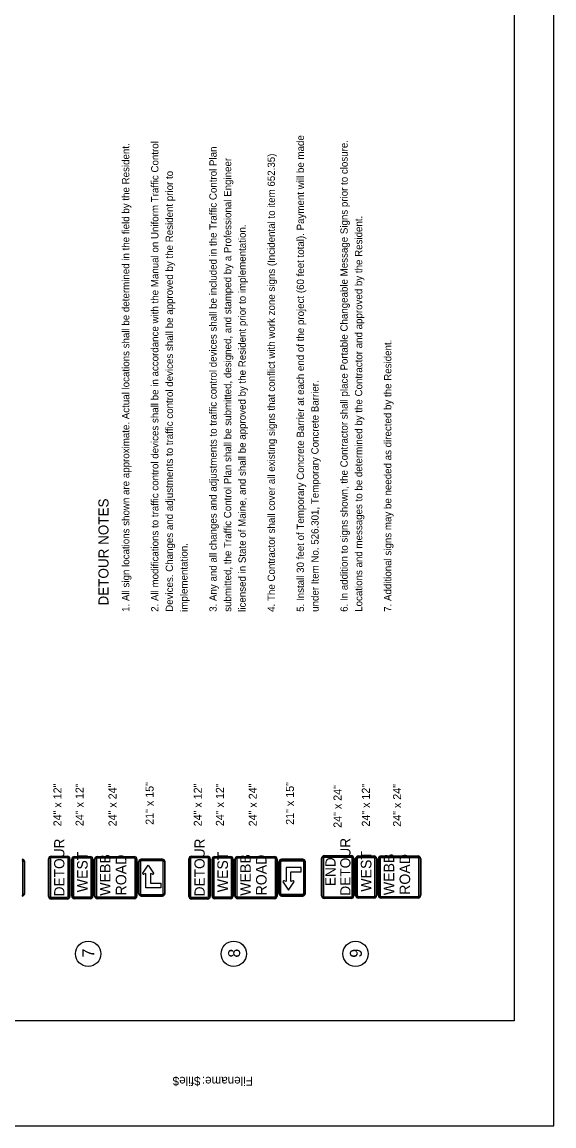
# Model space of a CAD drawing. Extents: x 1149904 to 1171904, y 589308 to 623636.
# Drawn here: x 1163721 to 1171904, y 589308 to 606292 of the extents above; entities that cross this region are included whole.
import ezdxf

# ---------------------------------------------------------------- set-up
doc = ezdxf.new("R2010")
doc.units = 0
for name, color, linetype in [('ANNOTATION', 7, 'Continuous'), ('BORDER', 7, 'Continuous'), ('D_Text_Standard', 7, 'Continuous'), ('Default', 7, 'Continuous'), ('PLOT BOUNDARY', 7, 'Continuous'), ('SIGNS TRAFFIC', 7, 'Continuous')]:
    doc.layers.add(name, color=color, linetype=linetype)

msp = doc.modelspace()

# ---------------------------------------------------------------- linework, layer by layer
at = {"layer": 'BORDER'}
msp.add_lwpolyline([(1150292, 590926), (1150292, 622926), (1171292, 622926), (1171292, 590926)], close=True, dxfattribs=at)
at = {"layer": 'D_Text_Standard'}
for centre in [(1164738, 591956), (1166978, 591956), (1168852, 591955)]:
    msp.add_circle(centre, 195, dxfattribs=at)
at = {"layer": 'PLOT BOUNDARY'}
msp.add_lwpolyline([(1171904, 589308), (1171904, 623308), (1149904, 623308), (1149904, 589308)], close=True, dxfattribs=at)
at = {"layer": 'SIGNS TRAFFIC'}
for p, q in [((1168013, 593215), (1168013, 593286)), ((1165854, 593042), (1165854, 592971))]:
    msp.add_line(p, q, dxfattribs=at)
for points in [[(1164169, 593458), (1164417, 593458)], [(1164169, 593458), (1164417, 593458)], [(1166328, 593458), (1166576, 593458)], [(1166328, 593458), (1166576, 593458)], [(1168371, 593467), (1168784, 593467)], [(1168371, 593467), (1168784, 593467)], [(1168371, 593457), (1168784, 593457)], [(1168893, 593462), (1169136, 593462)], [(1168893, 593462), (1169136, 593462)], [(1169245, 593462), (1169813, 593462)], [(1169245, 593462), (1169813, 593462)], [(1163735, 592885), (1163735, 593372)], [(1163752, 593372), (1163752, 592885)], [(1163762, 592885), (1163762, 593372)], [(1164128, 592840), (1164128, 593417)], [(1164128, 592840), (1164128, 593417)], [(1164139, 592840), (1164139, 593417)], [(1164156, 593417), (1164156, 592840)], [(1164169, 593448), (1164417, 593448)], [(1164417, 593431), (1164169, 593431)], [(1164431, 592840), (1164431, 593417)], [(1164448, 593417), (1164448, 592840)], [(1164458, 593417), (1164458, 592840)], [(1164458, 593417), (1164458, 592840)], [(1164485, 592844), (1164485, 593413)], [(1164485, 592844), (1164485, 593413)], [(1164495, 592844), (1164495, 593413)], [(1164512, 593413), (1164512, 592844)], [(1164526, 593453), (1164770, 593453)], [(1164526, 593453), (1164770, 593453)], [(1164526, 593443), (1164770, 593443)], [(1164770, 593426), (1164526, 593426)], [(1164783, 592844), (1164783, 593413)], [(1164800, 593413), (1164800, 592844)], [(1164810, 593413), (1164810, 592844)], [(1164810, 593413), (1164810, 592844)], [(1164837, 592844), (1164837, 593413)], [(1164837, 592844), (1164837, 593413)], [(1164847, 592844), (1164847, 593413)], [(1164864, 593413), (1164864, 592844)], [(1164878, 593453), (1165447, 593453)], [(1164878, 593453), (1165447, 593453)], [(1164878, 593443), (1165447, 593443)], [(1165447, 593426), (1164878, 593426)], [(1165460, 592844), (1165460, 593413)], [(1165477, 593413), (1165477, 592844)], [(1165487, 593413), (1165487, 592844)], [(1165487, 593413), (1165487, 592844)], [(1165514, 593372), (1165514, 592885)], [(1165514, 592885), (1165514, 593372)], [(1165524, 592885), (1165524, 593372)], [(1165541, 593372), (1165541, 592885)], [(1165880, 593413), (1165555, 593413)], [(1165555, 593413), (1165880, 593413)], [(1165555, 593403), (1165880, 593403)], [(1165880, 593386), (1165555, 593386)], [(1165578, 593199), (1165662, 593321), (1165745, 593199)], [(1165893, 592885), (1165893, 593372)], [(1165910, 593372), (1165910, 592885)], [(1165920, 592885), (1165920, 593372)], [(1165920, 593372), (1165920, 592885)], [(1166287, 592840), (1166287, 593417)], [(1166287, 592840), (1166287, 593417)], [(1166297, 592840), (1166297, 593417)], [(1166314, 593417), (1166314, 592840)], [(1166328, 593448), (1166576, 593448)], [(1166576, 593431), (1166328, 593431)], [(1166589, 592840), (1166589, 593417)], [(1166607, 593417), (1166607, 592840)], [(1166617, 593417), (1166617, 592840)], [(1166617, 593417), (1166617, 592840)], [(1166644, 592844), (1166644, 593413)], [(1166644, 592844), (1166644, 593413)], [(1166654, 592844), (1166654, 593413)], [(1166671, 593413), (1166671, 592844)], [(1166685, 593453), (1166928, 593453)], [(1166685, 593453), (1166928, 593453)], [(1166685, 593443), (1166928, 593443)], [(1166928, 593426), (1166685, 593426)], [(1166942, 592844), (1166942, 593413)], [(1166959, 593413), (1166959, 592844)], [(1166969, 593413), (1166969, 592844)], [(1166969, 593413), (1166969, 592844)], [(1166996, 592844), (1166996, 593413)], [(1166996, 592844), (1166996, 593413)], [(1167006, 592844), (1167006, 593413)], [(1167023, 593413), (1167023, 592844)], [(1167037, 593453), (1167605, 593453)], [(1167037, 593453), (1167605, 593453)], [(1167037, 593443), (1167605, 593443)], [(1167605, 593426), (1167037, 593426)], [(1167619, 592844), (1167619, 593413)], [(1167636, 593413), (1167636, 592844)], [(1167646, 593413), (1167646, 592844)], [(1167646, 593413), (1167646, 592844)], [(1167673, 592885), (1167673, 593372)], [(1167673, 593372), (1167673, 592885)], [(1167683, 593372), (1167683, 592885)], [(1167700, 592885), (1167700, 593372)], [(1167714, 593413), (1168039, 593413)], [(1168039, 593413), (1167714, 593413)], [(1168039, 593403), (1167714, 593403)], [(1167714, 593386), (1168039, 593386)], [(1168013, 593286), (1167785, 593286), (1167785, 593066), (1167751, 593077)], [(1168052, 593372), (1168052, 592885)], [(1168069, 592885), (1168069, 593372)], [(1168079, 593372), (1168079, 592885)], [(1168079, 592885), (1168079, 593372)], [(1168330, 592848), (1168330, 593426)], [(1168330, 592848), (1168330, 593426)], [(1168340, 592848), (1168340, 593426)], [(1168358, 593426), (1168358, 592848)], [(1168784, 593440), (1168371, 593440)], [(1168798, 592848), (1168798, 593426)], [(1168815, 593426), (1168815, 592848)], [(1168825, 593426), (1168825, 592848)], [(1168825, 593426), (1168825, 592848)], [(1168852, 592853), (1168852, 593421)], [(1168852, 592853), (1168852, 593421)], [(1168862, 592853), (1168862, 593421)], [(1168879, 593421), (1168879, 592853)], [(1168893, 593452), (1169136, 593452)], [(1169136, 593435), (1168893, 593435)], [(1169150, 592853), (1169150, 593421)], [(1169167, 593421), (1169167, 592853)], [(1169177, 593421), (1169177, 592853)], [(1169177, 593421), (1169177, 592853)], [(1169204, 592853), (1169204, 593421)], [(1169204, 592853), (1169204, 593421)], [(1169214, 592853), (1169214, 593421)], [(1169231, 593421), (1169231, 592853)], [(1169245, 593452), (1169813, 593452)], [(1169813, 593435), (1169245, 593435)], [(1169827, 592853), (1169827, 593421)], [(1169844, 593421), (1169844, 592853)], [(1169854, 593421), (1169854, 592853)], [(1169854, 593421), (1169854, 592853)], [(1165854, 592971), (1165626, 592971), (1165626, 593191), (1165593, 593180)], [(1165730, 593180), (1165697, 593191), (1165697, 593042), (1165854, 593042)], [(1167889, 593077), (1167856, 593066), (1167856, 593215), (1168013, 593215)], [(1167737, 593057), (1167820, 592936), (1167903, 593057)], [(1164169, 592826), (1164417, 592826)], [(1164417, 592809), (1164169, 592809)], [(1164417, 592798), (1164169, 592798)], [(1164417, 592798), (1164169, 592798)], [(1164526, 592831), (1164770, 592831)], [(1164770, 592814), (1164526, 592814)], [(1164770, 592803), (1164526, 592803)], [(1164770, 592803), (1164526, 592803)], [(1164878, 592831), (1165447, 592831)], [(1165447, 592814), (1164878, 592814)], [(1165447, 592803), (1164878, 592803)], [(1165447, 592803), (1164878, 592803)], [(1165555, 592871), (1165880, 592871)], [(1165880, 592854), (1165555, 592854)], [(1165555, 592844), (1165880, 592844)], [(1165880, 592844), (1165555, 592844)], [(1166328, 592826), (1166576, 592826)], [(1166576, 592809), (1166328, 592809)], [(1166576, 592798), (1166328, 592798)], [(1166576, 592798), (1166328, 592798)], [(1166685, 592831), (1166928, 592831)], [(1166928, 592814), (1166685, 592814)], [(1166928, 592803), (1166685, 592803)], [(1166928, 592803), (1166685, 592803)], [(1167037, 592831), (1167605, 592831)], [(1167605, 592814), (1167037, 592814)], [(1167605, 592803), (1167037, 592803)], [(1167605, 592803), (1167037, 592803)], [(1168039, 592871), (1167714, 592871)], [(1167714, 592854), (1168039, 592854)], [(1168039, 592844), (1167714, 592844)], [(1167714, 592844), (1168039, 592844)], [(1168371, 592835), (1168784, 592835)], [(1168784, 592817), (1168371, 592817)], [(1168784, 592807), (1168371, 592807)], [(1168784, 592807), (1168371, 592807)], [(1168893, 592839), (1169136, 592839)], [(1169136, 592822), (1168893, 592822)], [(1169136, 592812), (1168893, 592812)], [(1169136, 592812), (1168893, 592812)], [(1169245, 592839), (1169813, 592839)], [(1169813, 592822), (1169245, 592822)], [(1169813, 592812), (1169245, 592812)], [(1169813, 592812), (1169245, 592812)]]:
    msp.add_lwpolyline(points, dxfattribs=at)
for centre, radius, start, end in [((1164169, 593417), 41.2, 90, 180), ((1164169, 593417), 41.2, 90, 180), ((1164417, 593417), 41.2, 360, 90), ((1164417, 593417), 41.2, 360, 90), ((1166328, 593417), 41.2, 90, 180), ((1166328, 593417), 41.2, 90, 180), ((1166576, 593417), 41.2, 360, 90), ((1166576, 593417), 41.2, 360, 90), ((1168371, 593426), 41.2, 90, 180), ((1168371, 593426), 41.2, 90, 180), ((1168371, 593426), 30.9, 90, 180), ((1168784, 593426), 41.2, 360, 90), ((1168784, 593426), 41.2, 360, 90), ((1168784, 593426), 30.9, 360, 90), ((1168893, 593421), 40.6, 90, 180), ((1168893, 593421), 40.6, 90, 180), ((1169136, 593421), 40.6, 360, 90), ((1169136, 593421), 40.6, 360, 90), ((1169245, 593421), 40.6, 90, 180), ((1169245, 593421), 40.6, 90, 180), ((1169813, 593421), 40.6, 360, 90), ((1169813, 593421), 40.6, 360, 90), ((1163721, 593372), 40.6, 360, 90), ((1163721, 593372), 30.5, 360, 90), ((1163721, 593372), 13.5, 360, 90), ((1164169, 593417), 30.9, 90, 180), ((1164169, 593417), 13.7, 90, 180), ((1164417, 593417), 30.9, 360, 90), ((1164417, 593417), 13.7, 360, 90), ((1164526, 593413), 40.6, 90, 180), ((1164526, 593413), 40.6, 90, 180), ((1164526, 593413), 30.5, 90, 180), ((1164526, 593413), 13.5, 90, 180), ((1164770, 593413), 40.6, 360, 90), ((1164770, 593413), 40.6, 360, 90), ((1164770, 593413), 30.5, 360, 90), ((1164770, 593413), 13.5, 360, 90), ((1164878, 593413), 40.6, 90, 180), ((1164878, 593413), 40.6, 90, 180), ((1164878, 593413), 30.5, 90, 180), ((1164878, 593413), 13.5, 90, 180), ((1165447, 593413), 40.6, 360, 90), ((1165447, 593413), 40.6, 360, 90), ((1165447, 593413), 30.5, 360, 90), ((1165447, 593413), 13.5, 360, 90), ((1165555, 593372), 40.6, 90, 180), ((1165555, 593372), 40.6, 90, 180), ((1165555, 593372), 30.5, 90, 180), ((1165555, 593372), 13.5, 90, 180), ((1165880, 593372), 40.6, 360, 90), ((1165880, 593372), 40.6, 360, 90), ((1165880, 593372), 30.5, 360, 90), ((1165880, 593372), 13.5, 360, 90), ((1166328, 593417), 30.9, 90, 180), ((1166328, 593417), 13.7, 90, 180), ((1166576, 593417), 30.9, 360, 90), ((1166576, 593417), 13.7, 360, 90), ((1166685, 593413), 40.6, 90, 180), ((1166685, 593413), 40.6, 90, 180), ((1166685, 593413), 30.5, 90, 180), ((1166685, 593413), 13.5, 90, 180), ((1166928, 593413), 40.6, 360, 90), ((1166928, 593413), 40.6, 360, 90), ((1166928, 593413), 30.5, 360, 90), ((1166928, 593413), 13.5, 360, 90), ((1167037, 593413), 40.6, 90, 180), ((1167037, 593413), 40.6, 90, 180), ((1167037, 593413), 30.5, 90, 180), ((1167037, 593413), 13.5, 90, 180), ((1167605, 593413), 40.6, 360, 90), ((1167605, 593413), 40.6, 360, 90), ((1167605, 593413), 30.5, 360, 90), ((1167605, 593413), 13.5, 360, 90), ((1167714, 593372), 40.6, 90, 180), ((1167714, 593372), 40.6, 90, 180), ((1167714, 593372), 30.5, 90, 180), ((1167714, 593372), 13.5, 90, 180), ((1168039, 593372), 40.6, 360, 90), ((1168039, 593372), 40.6, 360, 90), ((1168039, 593372), 30.5, 360, 90), ((1168039, 593372), 13.5, 360, 90), ((1168371, 593426), 13.7, 90, 180), ((1168784, 593426), 13.7, 360, 90), ((1168893, 593421), 30.5, 90, 180), ((1168893, 593421), 13.5, 90, 180), ((1169136, 593421), 30.5, 360, 90), ((1169136, 593421), 13.5, 360, 90), ((1169245, 593421), 30.5, 90, 180), ((1169245, 593421), 13.5, 90, 180), ((1169813, 593421), 30.5, 360, 90), ((1169813, 593421), 13.5, 360, 90), ((1165589, 593192), 12.7, 145.6763, 287.8128), ((1165734, 593192), 12.7, 252.1872, 34.3237), ((1167748, 593065), 12.7, 72.1872, 214.3237), ((1167893, 593065), 12.7, 325.6763, 107.8128), ((1163721, 592885), 40.6, 270, 0), ((1163721, 592885), 30.5, 270, 0), ((1163721, 592885), 13.5, 270, 0), ((1164169, 592840), 41.2, 180, 270), ((1164169, 592840), 41.2, 180, 270), ((1164169, 592840), 30.9, 180, 270), ((1164169, 592840), 13.7, 180, 270), ((1164417, 592840), 41.2, 270, 360), ((1164417, 592840), 41.2, 270, 360), ((1164417, 592840), 30.9, 270, 360), ((1164417, 592840), 13.7, 270, 360), ((1164526, 592844), 40.6, 180, 270), ((1164526, 592844), 40.6, 180, 270), ((1164526, 592844), 30.5, 180, 270), ((1164526, 592844), 13.5, 180, 270), ((1164770, 592844), 40.6, 270, 360), ((1164770, 592844), 40.6, 270, 360), ((1164770, 592844), 30.5, 270, 360), ((1164770, 592844), 13.5, 270, 360), ((1164878, 592844), 40.6, 180, 270), ((1164878, 592844), 40.6, 180, 270), ((1164878, 592844), 30.5, 180, 270), ((1164878, 592844), 13.5, 180, 270), ((1165447, 592844), 40.6, 270, 360), ((1165447, 592844), 40.6, 270, 360), ((1165447, 592844), 30.5, 270, 360), ((1165447, 592844), 13.5, 270, 360), ((1165555, 592885), 40.6, 180, 270), ((1165555, 592885), 40.6, 180, 270), ((1165555, 592885), 30.5, 180, 270), ((1165555, 592885), 13.5, 180, 270), ((1165880, 592885), 40.6, 270, 0), ((1165880, 592885), 40.6, 270, 0), ((1165880, 592885), 30.5, 270, 0), ((1165880, 592885), 13.5, 270, 0), ((1166328, 592840), 41.2, 180, 270), ((1166328, 592840), 41.2, 180, 270), ((1166328, 592840), 30.9, 180, 270), ((1166328, 592840), 13.7, 180, 270), ((1166576, 592840), 41.2, 270, 360), ((1166576, 592840), 41.2, 270, 360), ((1166576, 592840), 30.9, 270, 360), ((1166576, 592840), 13.7, 270, 360), ((1166685, 592844), 40.6, 180, 270), ((1166685, 592844), 40.6, 180, 270), ((1166685, 592844), 30.5, 180, 270), ((1166685, 592844), 13.5, 180, 270), ((1166928, 592844), 40.6, 270, 360), ((1166928, 592844), 40.6, 270, 360), ((1166928, 592844), 30.5, 270, 360), ((1166928, 592844), 13.5, 270, 360), ((1167037, 592844), 40.6, 180, 270), ((1167037, 592844), 40.6, 180, 270), ((1167037, 592844), 30.5, 180, 270), ((1167037, 592844), 13.5, 180, 270), ((1167605, 592844), 40.6, 270, 360), ((1167605, 592844), 40.6, 270, 360), ((1167605, 592844), 30.5, 270, 360), ((1167605, 592844), 13.5, 270, 360), ((1167714, 592885), 40.6, 180, 270), ((1167714, 592885), 40.6, 180, 270), ((1167714, 592885), 30.5, 180, 270), ((1167714, 592885), 13.5, 180, 270), ((1168039, 592885), 40.6, 270, 0), ((1168039, 592885), 40.6, 270, 0), ((1168039, 592885), 30.5, 270, 0), ((1168039, 592885), 13.5, 270, 0), ((1168371, 592848), 41.2, 180, 270), ((1168371, 592848), 41.2, 180, 270), ((1168371, 592848), 30.9, 180, 270), ((1168371, 592848), 13.7, 180, 270), ((1168784, 592848), 41.2, 270, 360), ((1168784, 592848), 41.2, 270, 360), ((1168784, 592848), 30.9, 270, 360), ((1168784, 592848), 13.7, 270, 360), ((1168893, 592853), 40.6, 180, 270), ((1168893, 592853), 40.6, 180, 270), ((1168893, 592853), 30.5, 180, 270), ((1168893, 592853), 13.5, 180, 270), ((1169136, 592853), 40.6, 270, 360), ((1169136, 592853), 40.6, 270, 360), ((1169136, 592853), 30.5, 270, 360), ((1169136, 592853), 13.5, 270, 360), ((1169245, 592853), 40.6, 180, 270), ((1169245, 592853), 40.6, 180, 270), ((1169245, 592853), 30.5, 180, 270), ((1169245, 592853), 13.5, 180, 270), ((1169813, 592853), 40.6, 270, 360), ((1169813, 592853), 40.6, 270, 360), ((1169813, 592853), 30.5, 270, 360), ((1169813, 592853), 13.5, 270, 360)]:
    msp.add_arc(centre, radius, start, end, dxfattribs=at)

# ---------------------------------------------------------------- texts
at = {"layer": 'ANNOTATION'}
msp.add_text('DETOUR NOTES', height=155, rotation=90, dxfattribs=at).set_placement((1165051, 597315))
at = {"layer": 'BORDER'}
for s, p in [('$file$', (1166467, 590063)), ('Filename:', (1167273, 590063))]:
    msp.add_text(s, height=133.9, rotation=180, dxfattribs=at).set_placement(p)
at = {"layer": 'D_Text_Standard'}
for s, height, p in [('24" x 12"', 123.2, (1164327, 593917)), ('24" x 12"', 123.2, (1164667, 593921)), ('24" x 24"', 123.2, (1165174, 593917)), ('21" x 15"', 123.2, (1165745, 593941)), ('24" x 12"', 123.2, (1166486, 593917)), ('24" x 12"', 123.2, (1166826, 593921)), ('24" x 24"', 123.2, (1167333, 593917)), ('21" x 15"', 123.2, (1167904, 593941)), ('24" x 24"', 123.2, (1168636, 593895)), ('24" x 12"', 123.2, (1169072, 593914)), ('24" x 24"', 123.2, (1169552, 593911)), ('7', 184, (1164833, 591899)), ('8', 184, (1167076, 591897)), ('9', 184, (1168949, 591896))]:
    msp.add_text(s, height=height, rotation=90, dxfattribs=at).set_placement(p)
at = {"layer": 'Default'}
for s, p in [('5. Install 30 feet of Temporary Concrete Barrier at each end of the project (60 feet total). Payment will be made ', (1168059, 597218)), ('1. All sign locations shown are approximate. Actual locations shall be determined in the field by the Resident.', (1165371, 597218)), ('2. All modifications to traffic control devices shall be in accordance with the Manual on Uniform Traffic Control ', (1165819, 597218)), ('3. Any and all changes and adjustments to traffic control devices shall be included in the Traffic Control Plan ', (1166715, 597218)), ('6. In addition to signs shown, the Contractor shall place Portable Changeable Message Signs prior to closure.   ', (1168731, 597218)), ('submitted, the Traffic Control Plan shall be submitted, designed, and stamped by a Professional Engineer ', (1166939, 597218)), ('4. The Contractor shall cover all existing signs that conflict with work zone signs (Incidental to item 652.35)', (1167611, 597218)), ('Devices. Changes and adjustments to traffic control devices shall be approved by the Resident prior to ', (1166043, 597218)), ('licensed in State of Maine, and shall be approved by the Resident prior to implementation.', (1167163, 597218)), ('Locations and messages to be determined by the Contractor and approved by the Resident.', (1168955, 597218)), ('7. Additional signs may be needed as directed by the Resident.', (1169403, 597218)), ('under Item No. 526.301, Temporary Concrete Barrier.', (1168283, 597218)), ('implementation.', (1166267, 597218))]:
    msp.add_text(s, height=112, rotation=90, dxfattribs=at).set_placement(p)
at = {"layer": 'SIGNS TRAFFIC'}
for s, height, p in [('DETOUR', 157.5, (1164372, 592840)), ('DETOUR', 157.5, (1166531, 592840)), ('DETOUR', 157.5, (1168774, 592850)), ('WEST', 162.5, (1164729, 592902)), ('WEBB', 162.5, (1165081, 592849)), ('ROAD', 162.5, (1165325, 592854)), ('WEST', 162.5, (1166888, 592902)), ('WEBB', 162.5, (1167240, 592849)), ('ROAD', 162.5, (1167483, 592854)), ('WEST', 162.5, (1169096, 592911)), ('WEBB', 162.5, (1169448, 592858)), ('ROAD', 162.5, (1169692, 592863)), ('END', 157.5, (1168545, 592996))]:
    msp.add_text(s, height=height, rotation=90, dxfattribs=at).set_placement(p)

doc.saveas('drawing.dxf')
